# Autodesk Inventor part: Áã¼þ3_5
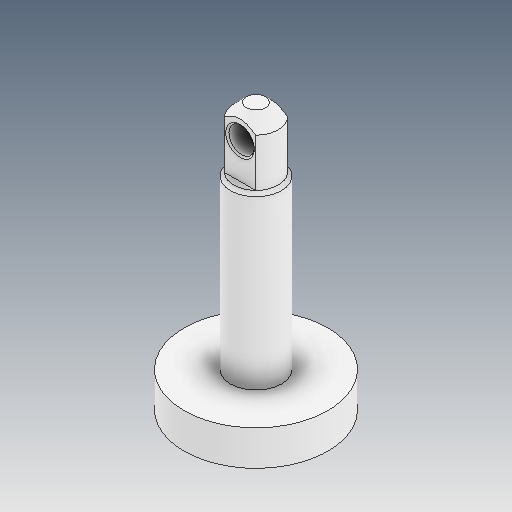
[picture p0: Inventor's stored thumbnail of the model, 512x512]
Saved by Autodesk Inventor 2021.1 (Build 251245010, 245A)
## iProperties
Created: 2021-05
Part Number: Áã¼þ3_5
Material: Ogólny
Document SubType Name: Modeling
Designer: user
Density: 1 g/cm^3
Appearance: Domyślna
Author: user
Revision Number: ÈÎºÎ
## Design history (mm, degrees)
feature "ÊäÈë1"
node "Bryła1"
